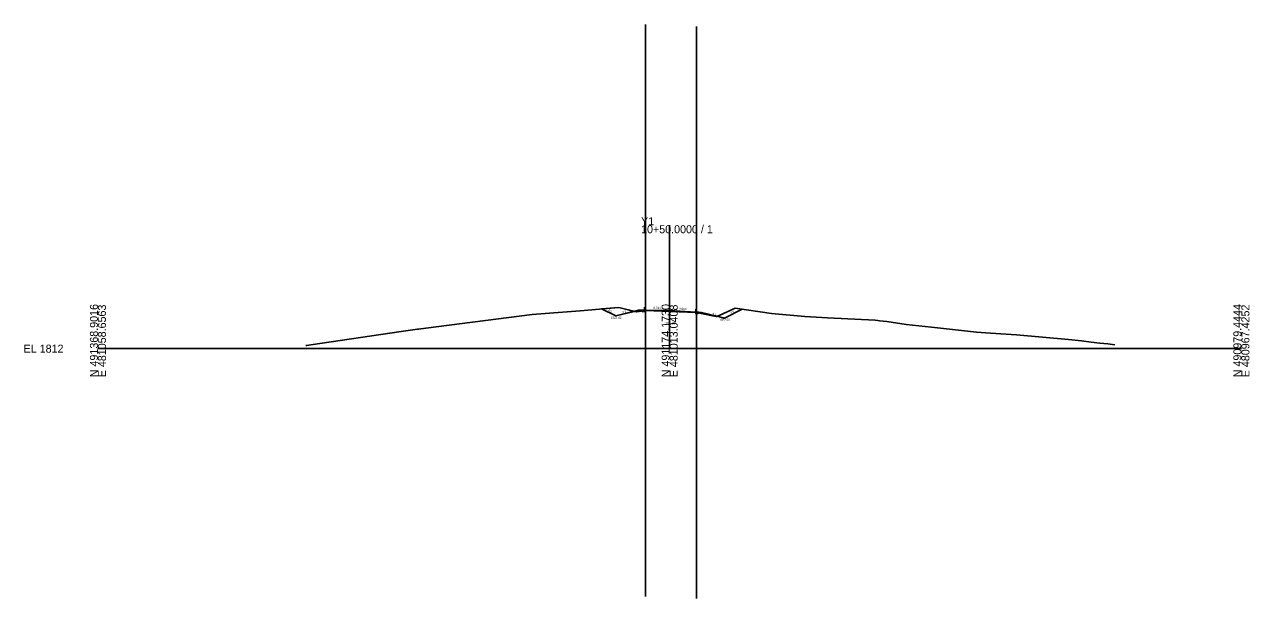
# Model space of a CAD drawing. Extents: x -26 to 403, y -10 to 6561.
# Drawn here: x -25.7 to 402.8, y 412.6 to 613.4 of the extents above; entities that cross this region are included whole.
import ezdxf

# ---------------------------------------------------------------- set-up
doc = ezdxf.new("R2010")
doc.units = 0
for name, color, linetype in [('Exist Cross Section Cell', 7, 'Continuous'), ('Exist XS Center Line Elevation Label', 7, 'Continuous'), ('Exist XS Ground Line', 7, 'Continuous'), ('Prop Road Sect_ Boring - Header (ID Tx)', 7, 'Continuous'), ('Prop Road Sect_ Material - Tx (Composite Desc)', 7, 'Continuous'), ('Prop XS Ditch Slope Text', 7, 'Continuous'), ('Prop XS Ditch Standard Text', 7, 'Continuous'), ('Prop XS EOT Tick Mark', 7, 'Continuous'), ('Prop XS Finish Grade', 7, 'Continuous'), ('Prop XS Finish Grade Earthwork', 7, 'Continuous'), ('Prop XS Finish Grade Pavement', 7, 'Continuous'), ('Prop XS Pvmt Edge Slope', 7, 'Continuous'), ('Prop XS SE Text', 7, 'Continuous'), ('Prop XS Side Slope Text', 7, 'Continuous'), ('Prop XS Subgrade Earthwork', 7, 'Continuous'), ('Scratch_Level_1', 7, 'Continuous'), ('Scratch_Level_4', 7, 'Continuous')]:
    doc.layers.add(name, color=color, linetype=linetype)

msp = doc.modelspace()

# ---------------------------------------------------------------- linework, layer by layer
at = {"layer": 'Exist Cross Section Cell'}
for p, q in [((200, 500), (200, 543.16)), ((0, 500), (200, 500)), ((200, 500), (400, 500))]:
    msp.add_line(p, q, dxfattribs=at)
at = {"layer": 'Exist XS Ground Line'}
msp.add_lwpolyline([(72.72, 501.1), (73.02, 501.15), (74.47, 501.37), (106.06, 505.96), (111.77, 506.76), (112.1, 506.83), (114.69, 507.16), (151.86, 511.9), (156.4, 512.28), (168.67, 513.28), (182.21, 514.39), (185.49, 513.57), (188.35, 512.86), (189.33, 513.01), (191.57, 513.38), (196.84, 513.35), (200.29, 513.27), (203.91, 512.97), (209.39, 512.62), (214.96, 511.49), (216.35, 511.24), (217.26, 511.63), (222.86, 514.15), (235.62, 512.27), (247.34, 511.25), (255.24, 510.78), (271.89, 509.93), (272.84, 509.83), (273.44, 509.77), (275.97, 509.44), (282.76, 508.49), (291.58, 507.52), (307.38, 505.74), (312.18, 505.45), (321.33, 504.8), (339.57, 503.18), (344.03, 502.74), (347.45, 502.3), (350.52, 501.88), (353.28, 501.63), (355.78, 501.39)], dxfattribs=at)
at = {"layer": 'Prop Road Sect_ Boring - Header (ID Tx)'}
for p, q in [((191.15, 513.5), (190.07, 513.45)), ((190.07, 513.45), (190.59, 512.93)), ((190.59, 512.93), (191.15, 513.5)), ((210.21, 512.71), (209.13, 512.78)), ((209.13, 512.78), (209.7, 512.2)), ((209.7, 512.2), (210.21, 512.71))]:
    msp.add_line(p, q, dxfattribs=at)
for points in [[(190.59, 512.93), (190.07, 513.45), (191.15, 513.5)], [(209.7, 512.2), (210.21, 512.71), (209.13, 512.78)]]:
    msp.add_lwpolyline(points, close=True, dxfattribs=at)
at = {"layer": 'Prop Road Sect_ Material - Tx (Composite Desc)'}
for points in [[(185.49, 513.57), (187.64, 513.04), (181.15, 511.42), (176.19, 513.9), (182.21, 514.39)], [(187.64, 513.04), (188.35, 512.86), (189.33, 513.01), (190.34, 513.18), (190.07, 513.45), (189.15, 513.42)], [(190.34, 513.18), (191.52, 513.37), (191.52, 512.95), (191.15, 512.95), (190.59, 512.93)], [(209.13, 512.63), (209.39, 512.62), (209.99, 512.49), (209.7, 512.2), (209.13, 512.24)], [(209.99, 512.49), (214.96, 511.49), (216.35, 511.24), (216.51, 511.31), (211.13, 512.66), (210.21, 512.71)], [(216.51, 511.31), (219.13, 510.66), (225.37, 513.78), (222.86, 514.15), (217.26, 511.63)]]:
    msp.add_lwpolyline(points, close=True, dxfattribs=at)
at = {"layer": 'Prop XS EOT Tick Mark'}
for p, q in [((191.15, 513.5), (191.15, 514.5)), ((209.13, 512.78), (209.13, 513.78))]:
    msp.add_line(p, q, dxfattribs=at)
at = {"layer": 'Prop XS Finish Grade'}
for p, q in [((191.15, 513.5), (190.07, 513.45)), ((209.13, 512.78), (210.21, 512.71))]:
    msp.add_line(p, q, dxfattribs=at)
at = {"layer": 'Prop XS Finish Grade Earthwork'}
for p, q in [((181.15, 511.42), (176.19, 513.9)), ((189.15, 513.42), (181.15, 511.42)), ((189.15, 513.42), (190.07, 513.45)), ((211.13, 512.66), (210.21, 512.71)), ((211.13, 512.66), (219.13, 510.66)), ((219.13, 510.66), (225.37, 513.78))]:
    msp.add_line(p, q, dxfattribs=at)
at = {"layer": 'Prop XS Finish Grade Pavement'}
for p, q in [((191.15, 513.5), (200, 513.32)), ((200, 513.32), (209.13, 512.78))]:
    msp.add_line(p, q, dxfattribs=at)
at = {"layer": 'Prop XS Pvmt Edge Slope'}
for p, q in [((191.15, 513.5), (190.59, 512.93)), ((209.13, 512.78), (209.7, 512.2))]:
    msp.add_line(p, q, dxfattribs=at)
at = {"layer": 'Prop XS Subgrade Earthwork'}
for p, q in [((190.59, 512.93), (190.07, 513.45)), ((191.15, 512.95), (190.59, 512.93)), ((191.15, 512.95), (191.52, 512.95)), ((191.52, 512.95), (191.52, 513.37)), ((191.52, 512.95), (191.52, 513.37)), ((209.13, 512.63), (209.13, 512.24)), ((209.13, 512.24), (209.7, 512.2)), ((209.7, 512.2), (210.21, 512.71))]:
    msp.add_line(p, q, dxfattribs=at)
at = {"layer": 'Scratch_Level_1'}
for p, q in [((191.52, 613.37), (191.52, 413.37)), ((209.34, 612.62), (209.34, 412.62))]:
    msp.add_line(p, q, dxfattribs=at)
at = {"layer": 'Scratch_Level_4'}
msp.add_line((191.52, 513.37), (209.13, 512.63), dxfattribs=at)

# ---------------------------------------------------------------- texts
at = {"layer": 'Exist Cross Section Cell'}
for s, p in [('Y1', (190, 543.16)), ('10+50.0000 / 1', (190, 540.36)), ('EL 1812', (-26, 498.6))]:
    msp.add_text(s, height=2.8, dxfattribs=at).set_placement(p)
for s, p in [('N 491368.9016', (0, 490)), ('E 481058.6563', (2.8, 490)), ('N 491174.1730', (200, 490)), ('E 481013.0408', (202.8, 490)), ('N 490979.4444', (400, 490)), ('E 480967.4252', (402.8, 490))]:
    msp.add_text(s, height=2.8, rotation=90, dxfattribs=at).set_placement(p)
at = {"layer": 'Exist XS Center Line Elevation Label'}
msp.add_text('1825.28', height=0.75, dxfattribs=at).set_placement((198.18, 508.53))
at = {"layer": 'Prop XS Ditch Slope Text'}
for rotation, p in [(14.0361, (183.49, 512.35)), (345.9639, (214.91, 511.94))]:
    msp.add_text('4:1', height=0.75, rotation=rotation, dxfattribs=at).set_placement(p)
at = {"layer": 'Prop XS Ditch Standard Text'}
for s, p in [('1823.42', (179.38, 510.49)), ('1822.66', (217.34, 509.73))]:
    msp.add_text(s, height=0.75, dxfattribs=at).set_placement(p)
at = {"layer": 'Prop XS SE Text'}
for s, rotation, p in [('0.019', 358.8924, (194.36, 513.93)), ('0.060', 356.5664, (203.25, 513.63))]:
    msp.add_text(s, height=0.75, rotation=rotation, dxfattribs=at).set_placement(p)
at = {"layer": 'Prop XS Side Slope Text'}
for rotation, p in [(333.4352, (178.42, 513.26)), (26.5648, (221.46, 512.04))]:
    msp.add_text('2:1', height=0.75, rotation=rotation, dxfattribs=at).set_placement(p)

doc.saveas('drawing.dxf')
